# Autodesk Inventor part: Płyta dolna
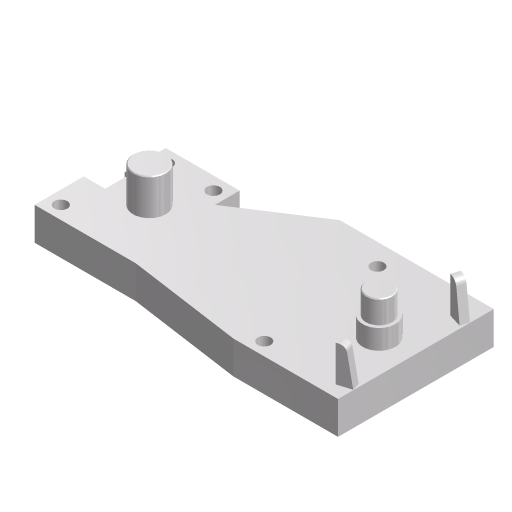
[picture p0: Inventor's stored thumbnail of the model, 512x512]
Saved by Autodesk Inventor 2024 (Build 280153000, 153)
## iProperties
Company: ATC
Shininess: 20.0
Angle Display Precision: 2
Document Length Units: 11269
Document Angle Units: 11279
Document Time Units: 11290
Document Mass Units: 11283
Document Length Units Precision: 3
Document Angle Units Precision: 2
Created: 2023-03
Part Number: Płyta dolna
Material: Stal węglowa
Document SubType Name: Modelowanie
Designer: Andrzej Jaskulski
Density: 7.87 g/cm^3
Stock Number: Płyta dolna
Appearance: Kurs-AJ
Checked By: A.J.
Engr Approved By: Andrzej Jaskulski
Mfg Approved By: Andrzej Jaskulski
Authority: A.J.
Density: 0.0
Volumn: 0.0
Area: 0.0
PropertySet Name: Model Information
Control State: 0
Master: False
Checked Out: False
Title: A.J.: Kurs R2024-MEP
Author: Andrzej Jaskulski
Revision Number: 1/24
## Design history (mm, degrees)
node "Bryła1"
node "Korpusy bryłowe"
node "Korpusy powierzchniowe"
node "Początek"
sketch "Szkic1"
  geometry: L1 (60, 60)-(60, 90); L2 (60, 90)-(73, 90) reference; L3 (73, 90)-(73, 105) reference; L4 (73, 105)-(70, 105) reference; L5 (70, 105)-(70, 130) reference; L6 (70, 130)-(115, 130) reference; L7 (115, 130)-(115, 115) reference; L8 (115, 115)-(161.127, 144.955); L9 (161.127, 144.955)-(255, 144.955); L10 (60, 60)-(121.629, 60) reference; L11 (121.629, 60)-(191.251, 50) reference; L12 (191.251, 50)-(255, 50) reference; L13 (255, 50)-(255, 144.955); L14 (95, 95)-(235, 95); C1 r 10 at (95, 95); C2 r 4 at (68, 68); C3 r 4 at (78, 122); C4 r 4 at (197, 131.955); C5 r 4 at (202, 58); C6 r 4 at (107, 122); C7 r 10 at (235, 95); A1 r 40 centre (235, 95) between (205.142, 121.617) and (210.142, 63.662)
  constraints: 28 end point, 8 centre point, 6 horizontal, 4 vertical, 2 coincident, 2 perpendicular, 2 point on circle, 1 horizontal alignment, 1 vertical alignment, 1 other
  dimensions: "d0" = 20 diameter of C1; "d5" = 10 distance between parallel lines of L5 L1; "d6" = 8 diameter of C3; "d7" = 8 diameter of C6 (= d6); "d8" = 8 diameter of C2 (= d6); "d9" = 8 diameter of C4 (= d6); "d10" = 8 diameter of C5 (= d6); "d11" = 8 distance from line of L6 C3.centre; "d12" = 8 distance from line of C3.centre L5 (= d11); "d13" = 8 distance from line of C6.centre L7 (= d11); "d14" = 8 distance from line of C2.centre L10 (= d11); "d15" = 8 distance from line of C2.centre L1 (= d11); "d20" = 35 distance from line of L10 L14.start; "d21" = 35 distance from line of L1 L14.start (= d20); "d22" = 40 radius of A1; "d25" = 20 diameter of C7 (= d0); "d26" = 20 distance from line of A1.centre L13; "d54" = 90 horizontal distance of C4.centre C6.centre; "d55" = 134 horizontal distance of C5.centre C2.centre; "d56" = 13 distance from line of L9 C4.centre; "d57" = 8 distance from line of C5.centre L12; "d58" = 140 distance of L14.start L14.end; "d59" = 15 distance of L6.end L7.end; "d60" = 55 distance of L7.end L8.end; "d61" = 57 deg angle of L7 L8
extrude "Wyciągnięcie proste1" new body sketch "Szkic1" distance "d1" = 20; taper "d2" = 0 deg
extrude "Wyciągnięcie proste2" join sketch "Szkic1" distance "d27" = 12; taper "d28" = 0 deg
sketch "Szkic2"
  geometry: C1 r 10 at (0, 0) reference; C2 r 8 at (0, 0)
  constraints: 1 centre point, 1 coincident
  dimensions: "d34" = 2 radial gap between concentric circles of C2 C1
extrude "Wyciągnięcie proste3" join sketch "Szkic2" distance "d35" = 14; taper "d36" = 0 deg
chamfer "Faza1" distance "d39" = 0.5; stored, may be unused: second distance "d40" = 0.5, angle "d64" = 45 deg
extrude "Wyciągnięcie proste5" join sketch "Szkic1" distance "d46" = 22; taper "d47" = 0 deg
chamfer "Faza2" distance "d48" = 0.5; stored, may be unused: second distance "d49" = 0.5, angle "d65" = 45 deg
node "Płaszczyzna konstrukcyjna3"
sketch "Tory Suwaków"
  geometry: L1 (154.596, 10)-(275, 10); L2 (275, 10)-(275, 241.921); L3 (255, 144.955)-(255, 50) reference; L4 (255, 50)-(191.251, 50) reference
  constraints: 4 end point, 1 parallel
  dimensions: "d63" = 20 distance between parallel lines of L3 L2; "d67" = 40 distance between parallel lines of L4 L1
sketch "Szkic5"
  geometry: L1 (239.386, 80.655)-(246.615, 57.01) reference; L2 (246.634, 133.054)-(239.386, 109.345) reference; L3 (246.615, 57.01)-(251.396, 58.472); L4 (251.396, 58.472)-(249.934, 63.253); L5 (249.934, 63.253)-(245.153, 61.791); L6 (246.634, 133.054)-(251.416, 131.592); L7 (251.416, 131.592)-(249.954, 126.81); L8 (249.954, 126.81)-(245.172, 128.272)
  constraints: 16 end point, 4 perpendicular, 3 equal length, 2 parallel, 2 point on line, 2 other
  dimensions: "d68" = 5 distance of L3.end L4.end
extrude "Wyciągnięcie proste6" join sketch "Szkic5" distance "d69" = 22; taper "d70" = 0 deg
feature "Szkic powierzchni1" dims angle "d71" = 9 deg
feature "Szkic powierzchni2" dims angle "d72" = 9 deg
fillet "Zaokrąglenie1" dims "d73" = 4
node "Płaszczyzna YZ"
node "Płaszczyzna XZ"
node "Płaszczyzna XY"
node "Oś X"
node "Oś Y"
node "Oś Z"
node "Punkt środkowy"
other parameters: "d29" = 0, "d30" = 0, "d31" = 0, "d32" = 0, "d33" = 0, "d50" = 6
